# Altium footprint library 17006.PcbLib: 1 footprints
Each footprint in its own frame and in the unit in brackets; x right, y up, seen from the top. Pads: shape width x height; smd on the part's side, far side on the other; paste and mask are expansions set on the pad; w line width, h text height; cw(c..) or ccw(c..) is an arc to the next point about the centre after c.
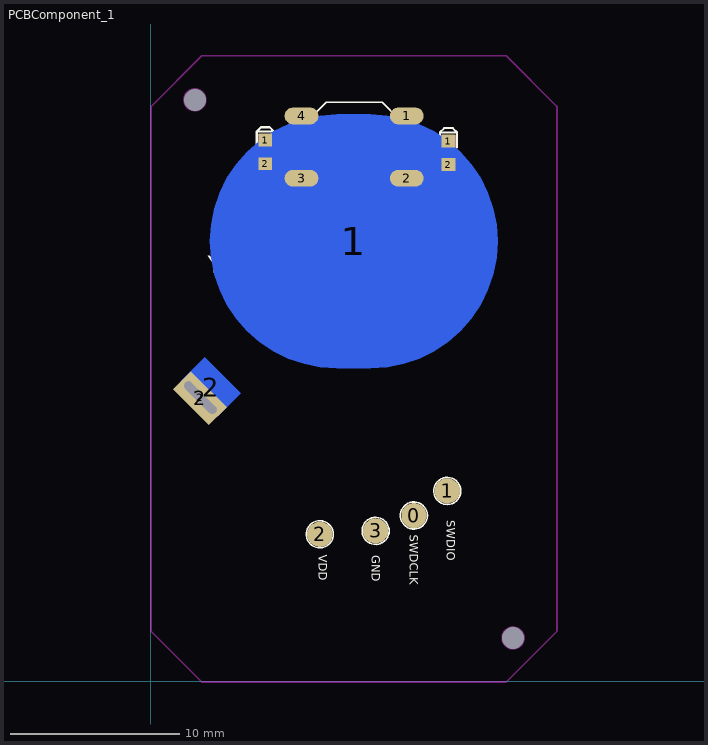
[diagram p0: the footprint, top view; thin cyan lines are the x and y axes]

## PCBComponent_1 [mm]
pads (18):
  round 0 hole 1.3: 0(2.609,34.351) 0(21.412,2.552)
  round 1.5 smd: 0(15.555,9.782) 1(17.52,11.237) 2(9.99,8.677) 3(13.29,8.877)
  rect 0.813x0.762 smd: 1(6.77,31.969) 1(17.594,31.918) 2(6.77,30.572) 2(17.594,30.521)
  oval 17x15 smd far side: 1(12,25.987)
  oval 2x1 smd: 1(15.132,33.398) 2(15.132,29.718) 3(8.912,29.718) 4(8.912,33.398)
  rect 1.5x3 smd rot 45: 2(2.91,16.717)
  oval 0.8x3 hole 0.5 slot 2.5 at 135 deg rot 45: 2(2.937,16.756)
  rect 2x3 smd far side rot 45: 2(3.55,17.357)
Top Overlay:
  circle w0.1: c12.022,31.558 r1
  circle w0.1: c12.022,31.558 r1.5
  circle w0.1: c15.55,9.787 r0.8
  circle w0.1: c17.52,11.237 r0.8
  circle w0.1: c13.29,8.877 r0.8
  circle w0.1: c9.99,8.677 r0.8
  lines w0.1: 9.372,29.908 10.372,28.908 13.672,28.908 14.672,29.908 14.672,33.208 13.672,34.208 10.372,34.208 9.372,33.208 9.372,29.908
  lines w0.127: 6.262,30.953 6.262,30.064 7.278,30.064 7.278,30.953 ; 6.262,31.588 6.262,32.477 ; 7.278,31.588 7.278,32.477 ; 17.086,30.902 17.086,30.013 18.102,30.013 18.102,30.902 ; 17.086,31.537 17.086,32.426 ; 18.102,31.537 18.102,32.426 ; 6.262,32.477 7.278,32.477 ; 6.262,32.477 6.516,32.731 7.024,32.731 7.278,32.477 ; 17.086,32.426 18.102,32.426 ; 17.086,32.426 17.34,32.68 17.848,32.68 18.102,32.426
  text "YJ-17006-NRF52832" at 3.38,24.127 h1
  text "SWDIO" at 17.48,9.517 h0.5
  text "SWDCLK" at 15.31,8.637 h0.5
  text "GND" at 13.06,7.437 h0.5
  text "VDD" at 9.92,7.457 h0.5
Bottom Overlay:
  circle w0.1: c12.012,25.452 r10
  circle w0.1: c12.012,25.452 r8.5
  circle w0.1: c12.02,6.847 r7.5
  circle w0.1: c12.012,6.852 r6
  lines w0.1: 3.527,18.881 4.941,17.466 ; 3.699,16.288 2.32,17.667 4.061,19.415 ; 3.74,16.267 5.424,17.95 ; 3.81,19.163 5.224,17.749
Keep-Out Layer:
  circle w0.1: c2.609,34.352 r0.65
  circle w0.1: c21.412,2.552 r0.65
  lines w0.1: 0.012,2.952 0.012,33.952 3.012,36.952 21.012,36.952 24.012,33.952 24.012,2.952 21.012,-0.048 3.012,-0.048 0.012,2.952
Mechanical 7:
  lines w0.1: 6.331,30.57 7.209,30.57 ; 6.331,30.67 7.209,30.67 ; 6.331,31.87 7.209,31.87 ; 6.331,31.97 7.209,31.97 ; 17.155,30.519 18.033,30.519 ; 17.155,30.619 18.033,30.619 ; 17.155,31.819 18.033,31.819 ; 17.155,31.919 18.033,31.919 ; 6.331,30.27 6.331,32.27 7.209,32.27 7.209,30.27 6.331,30.27 ; 17.155,30.219 17.155,32.219 18.033,32.219 18.033,30.219 17.155,30.219
  text "LED_G" at 17.469,31.719 h0.3
  text "LED_G" at 6.645,31.77 h0.3
3D body: height 0.6, standoff 0, extent 17.194,30.402 17.994,32.023
3D body: height 0.6, standoff 0, extent 6.37,30.453 7.17,32.074
3D body: height 1, standoff 0, extent 9.355,28.891 14.689,34.225
3D body: height 0.2, standoff 0, extent 14.181,29.399 15.578,30.034
3D body: height 0.2, standoff 0, extent 8.466,33.082 9.863,33.717
3D body: height 0.2, standoff 0, extent 14.308,33.082 15.578,33.59
3D body: height 0.2, standoff 0, extent 8.466,29.526 9.736,30.034
3D body: height 1.5, standoff 1, extent 11.022,30.56 13.014,32.556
